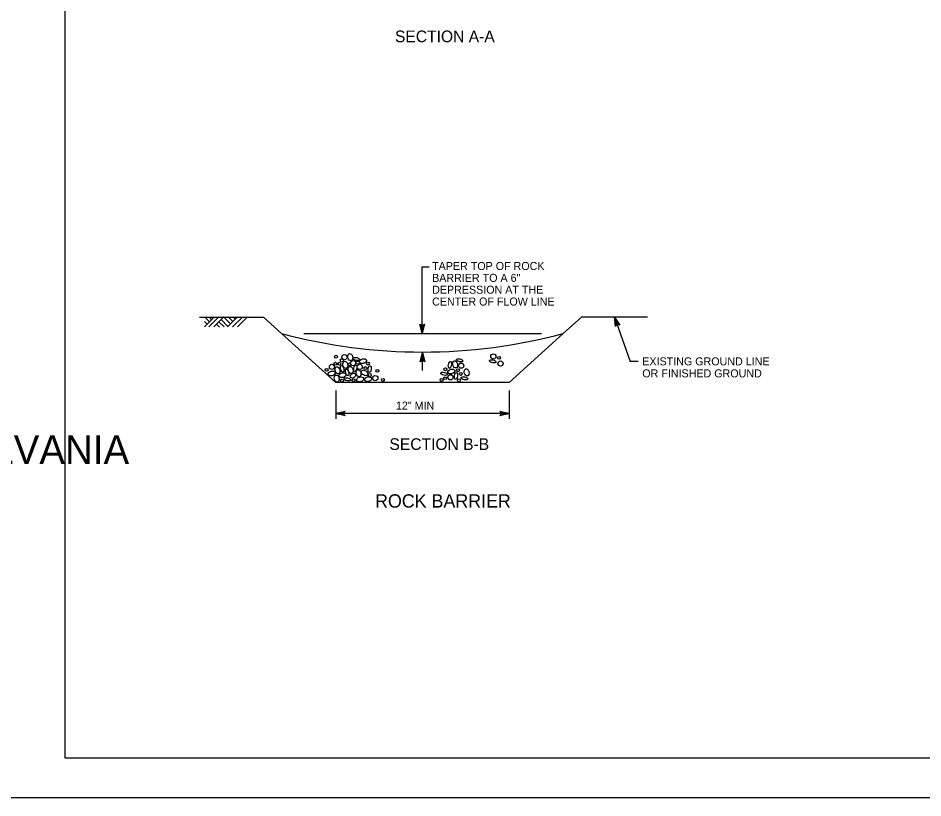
# Model space of a CAD drawing. Extents: x 636462 to 638208, y 299350 to 300538.
# Drawn here: x 637325.5 to 637664.4, y 299350.4 to 299642.7 of the extents above; entities that cross this region are included whole.
import ezdxf

# ---------------------------------------------------------------- set-up
doc = ezdxf.new("R2010")
doc.units = 0
for name, color, linetype in [('1', 7, 'Continuous'), ('Default', 7, 'Continuous'), ('PLT-BNDY', 7, 'Continuous')]:
    doc.layers.add(name, color=color, linetype=linetype)

msp = doc.modelspace()

# ---------------------------------------------------------------- linework, layer by layer
at = {"layer": '1'}
msp.add_lwpolyline([(638128.91, 299365.45), (638128.91, 299929.45), (637342.91, 299929.45), (637342.91, 299365.45), (638128.91, 299365.45), (638128.91, 299391.81), (637928.91, 299391.81), (637928.91, 299456.49), (638128.91, 299456.49), (638128.91, 299485.45), (637928.91, 299485.45), (637928.91, 299365.45), (638007.72, 299365.45), (638007.72, 299391.81), (638007.72, 299365.45), (638084.72, 299365.45), (638084.72, 299391.81), (638084.72, 299379.49), (638128.91, 299379.49)], dxfattribs=at)
at = {"layer": 'Default'}
for p, q in [((637476.85, 299549.5), (637479.38, 299549.5)), ((637476.85, 299524.52), (637476.85, 299549.5)), ((637393.4, 299530.67), (637417.37, 299530.67)), ((637395.22, 299526.96), (637398.92, 299530.67)), ((637395.37, 299530.67), (637397.15, 299528.9)), ((637396.95, 299526.97), (637400.67, 299530.69)), ((637396.97, 299530.67), (637397.95, 299529.69)), ((637398.75, 299526.97), (637402.46, 299530.69)), ((637402.38, 299530.69), (637405.01, 299528.07)), ((637403.9, 299526.98), (637407.63, 299530.72)), ((637404.17, 299530.7), (637405.88, 299528.99)), ((637405.79, 299526.98), (637409.46, 299530.67)), ((637405.98, 299530.7), (637406.8, 299529.88)), ((637407.58, 299526.98), (637411.25, 299530.67)), ((637417.37, 299530.67), (637424.14, 299524.52)), ((637536.46, 299530.67), (637529.68, 299524.52)), ((637561.23, 299530.67), (637536.46, 299530.67)), ((637548.84, 299530.67), (637554.76, 299514.06)), ((637395.3, 299528.96), (637396.26, 299528)), ((637399.8, 299528.02), (637400.91, 299526.91)), ((637400.69, 299528.92), (637402.64, 299526.97)), ((637401.49, 299529.72), (637404.06, 299527.16)), ((637444.47, 299506.08), (637424.14, 299524.52)), ((637432.54, 299524.52), (637521.46, 299524.52)), ((637509.36, 299506.08), (637529.68, 299524.52)), ((637476.91, 299510.62), (637476.91, 299517.57)), ((637557.76, 299514.06), (637554.76, 299514.06)), ((637509.36, 299506.08), (637444.47, 299506.08)), ((637444.47, 299503.19), (637444.47, 299492.56)), ((637509.36, 299503.19), (637509.36, 299492.56)), ((637509.36, 299494.49), (637444.47, 299494.49))]:
    msp.add_line(p, q, dxfattribs=at)
for points in [[(637549.32, 299527.41), (637549.2, 299527.08), (637548.84, 299530.67), (637549.32, 299527.41), (637549.61, 299527.72), (637548.84, 299530.67), (637550.1, 299527.9), (637550.52, 299527.85), (637548.84, 299530.67), (637550.85, 299527.67), (637550.52, 299527.85)], [(637477.48, 299527.76), (637477.71, 299528.02), (637476.85, 299524.52), (637477.48, 299527.76), (637477.11, 299527.56), (637476.85, 299524.52), (637476.59, 299527.55), (637476.21, 299527.74), (637476.85, 299524.52), (637475.96, 299528.02), (637476.21, 299527.74)], [(637476.27, 299514.17), (637476.04, 299513.9), (637476.9, 299517.4), (637476.27, 299514.17), (637476.64, 299514.36), (637476.9, 299517.4), (637477.16, 299514.37), (637477.54, 299514.19), (637476.9, 299517.4), (637477.79, 299513.9), (637477.54, 299514.19)], [(637447.7, 299493.86), (637447.97, 299493.63), (637444.47, 299494.49), (637447.7, 299493.86), (637447.5, 299494.23), (637444.47, 299494.49), (637447.5, 299494.75), (637447.68, 299495.13), (637444.47, 299494.49), (637447.96, 299495.38), (637447.68, 299495.13)], [(637506.13, 299495.13), (637505.86, 299495.35), (637509.36, 299494.49), (637506.13, 299495.13), (637506.32, 299494.76), (637509.36, 299494.49), (637506.33, 299494.23), (637506.15, 299493.86), (637509.36, 299494.49), (637505.87, 299493.61), (637506.15, 299493.86)]]:
    msp.add_lwpolyline(points, dxfattribs=at)
for centre, radius in [((637444.33, 299513.18), 0.548), ((637444.53, 299515.78), 0.548), ((637445.8, 299513.18), 0.548), ((637446.67, 299514.45), 0.548), ((637447.69, 299515.65), 0.974), ((637450.97, 299513.41), 0.974), ((637452.66, 299513.57), 0.548), ((637456.49, 299513.24), 0.548), ((637503.48, 299515.92), 0.974), ((637505.6, 299515.38), 0.548), ((637506.15, 299513.25), 0.974), ((637440.99, 299510.9), 0.548), ((637443.01, 299511.98), 0.974), ((637449.54, 299512.91), 0.548), ((637453.42, 299511.99), 0.974), ((637455.54, 299511.54), 0.548), ((637460.03, 299510.5), 0.548), ((637485.49, 299511.11), 0.548), ((637490.27, 299510.74), 0.548), ((637491.45, 299512.44), 0.974), ((637446.77, 299506.87), 0.548), ((637451.11, 299507), 0.548), ((637457.19, 299508.94), 0.548), ((637459.25, 299507.77), 0.974), ((637462.1, 299507.1), 0.548), ((637484.08, 299507.1), 0.548), ((637485.42, 299507.76), 0.548), ((637487.44, 299508.1), 0.974), ((637490.56, 299506.96), 0.548), ((637491.3, 299509.37), 0.548)]:
    msp.add_circle(centre, radius, dxfattribs=at)
msp.add_arc((637476.91, 299721.41), 203.84, 254.9967, 285.0033, dxfattribs=at)
for centre, major_axis, ratio in [((637449.88, 299515.63), (0.33, -1.32), 0.648413), ((637448.01, 299512.77), (0.33, -1.32), 0.648413), ((637452.17, 299514.94), (1.25, -0.26), 0.431289), ((637454.65, 299514.15), (1.32, 0.33), 0.648413), ((637487.2, 299512.76), (0.26, 1.25), 0.431289), ((637489.16, 299512.9), (0.33, -1.32), 0.648413), ((637490.86, 299514.47), (1.25, -0.26), 0.431289), ((637503.22, 299514.07), (1.25, -0.26), 0.431289), ((637442.89, 299509.53), (1.32, 0.33), 0.648413), ((637445.08, 299510.72), (0.33, -1.32), 0.648413), ((637446.85, 299511.28), (-0.4, 1.21), 0.431289), ((637448.72, 299509.94), (-0.4, 1.21), 0.431289), ((637450.02, 299510.85), (0.33, -1.32), 0.648413), ((637451.75, 299511.44), (0.26, 1.25), 0.431289), ((637452.95, 299509.63), (0.33, -1.32), 0.648413), ((637455.23, 299509.72), (1.17, -0.7), 0.648413), ((637457.13, 299511.16), (0.26, 1.25), 0.431289), ((637487.72, 299510.27), (1.32, 0.33), 0.648413), ((637493.45, 299509.92), (0.33, -1.32), 0.648413), ((637444.8, 299507.62), (0.33, -1.32), 0.648413), ((637446.96, 299508.87), (1.32, 0.33), 0.648413), ((637448.83, 299507.32), (1.25, -0.26), 0.431289), ((637450.92, 299508.73), (-0.85, -0.709), 0.707617), ((637453.58, 299507.33), (1.32, 0.33), 0.648413), ((637456.58, 299507.4), (1.32, 0.33), 0.648413), ((637485.04, 299509.4), (1.25, -0.26), 0.431289), ((637489.47, 299508.62), (0.26, 1.25), 0.431289), ((637492.66, 299507.72), (1.25, -0.26), 0.431289)]:
    msp.add_ellipse(centre, major_axis=major_axis, ratio=ratio, start_param=0, end_param=6.283175, dxfattribs=at)
at = {"layer": 'PLT-BNDY'}
msp.add_lwpolyline([(637302.91, 299944.45), (638143.91, 299944.45), (638143.91, 299350.45), (637302.91, 299350.45)], close=True, dxfattribs=at)

# ---------------------------------------------------------------- texts
at = {"layer": '1'}
msp.add_text('COMMONWEALTH OF PENNSYLVANIA', height=10.7834, dxfattribs=at).set_placement((637101.07, 299475.59))
at = {"layer": 'Default'}
for s, height, p in [('SECTION A-A', 4.3721, (637466.63, 299633.68)), ('TAPER TOP OF ROCK', 2.998, (637480.53, 299548.3)), ('BARRIER TO A 6"', 2.998, (637480.53, 299543.86)), ('DEPRESSION AT THE', 2.998, (637480.53, 299539.42)), ('CENTER OF FLOW LINE', 2.998, (637480.53, 299534.98)), ('EXISTING GROUND LINE ', 2.998, (637559.26, 299512.56)), ('OR FINISHED GROUND', 2.998, (637559.26, 299508.06)), ('12" MIN', 2.998, (637466.99, 299495.99)), ('SECTION B-B', 4.3721, (637464.55, 299480.86)), ('ROCK BARRIER', 4.9967, (637459.16, 299459.25))]:
    msp.add_text(s, height=height, dxfattribs=at).set_placement(p)

doc.saveas('drawing.dxf')
